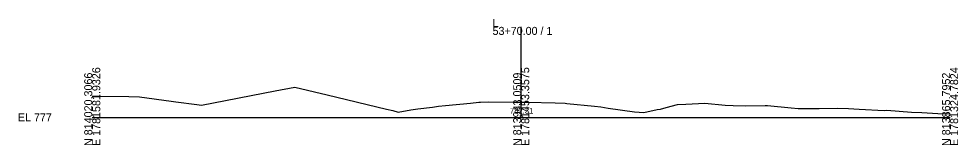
# Model space of a CAD drawing. Extents: x -26 to 7903, y -10 to 9573.
# Drawn here: x 7574.3 to 7902.8, y -9.7 to 34.4 of the extents above; entities that cross this region are included whole.
import ezdxf

# ---------------------------------------------------------------- set-up
doc = ezdxf.new("R2010")
doc.units = 0
for name, color, linetype in [('Exist Cross Section Cell', 7, 'Continuous'), ('Exist XS Center Line Elevation Label', 7, 'Continuous'), ('Exist XS Ground Line', 7, 'Continuous')]:
    doc.layers.add(name, color=color, linetype=linetype)

msp = doc.modelspace()

# ---------------------------------------------------------------- linework, layer by layer
at = {"layer": 'Exist Cross Section Cell'}
for p, q in [((7750, 0), (7750, 31.56)), ((7600, 0), (7750, 0)), ((7750, 0), (7900, 0))]:
    msp.add_line(p, q, dxfattribs=at)
at = {"layer": 'Exist XS Ground Line'}
for p, q in [((7663.97, 9.21), (7670.88, 10.52)), ((7670.88, 10.52), (7682.17, 7.82)), ((7600, 7.34), (7602.91, 7.37)), ((7602.91, 7.37), (7612.85, 7.28)), ((7612.85, 7.28), (7616.51, 7.11)), ((7616.51, 7.11), (7627.64, 5.69)), ((7638.15, 4.29), (7663.97, 9.21)), ((7682.17, 7.82), (7702.92, 2.91)), ((7627.64, 5.69), (7629.25, 5.41)), ((7629.25, 5.41), (7636.61, 4.48)), ((7636.61, 4.48), (7638.15, 4.29)), ((7713.81, 3.03), (7718.94, 3.6)), ((7718.94, 3.6), (7721.03, 3.92)), ((7721.03, 3.92), (7723.52, 4.14)), ((7723.52, 4.14), (7732.24, 4.99)), ((7732.24, 4.99), (7735.14, 5.26)), ((7735.14, 5.26), (7735.83, 5.29)), ((7735.83, 5.29), (7738.42, 5.41)), ((7738.42, 5.41), (7747.3, 5.34)), ((7747.3, 5.34), (7749.65, 5.32)), ((7749.65, 5.32), (7750, 5.31)), ((7750, 5.31), (7752.22, 5.26)), ((7752.22, 5.26), (7761.88, 5.08)), ((7761.88, 5.08), (7765.33, 4.92)), ((7765.33, 4.92), (7766.01, 4.89)), ((7766.01, 4.89), (7775.68, 3.92)), ((7775.68, 3.92), (7777.91, 3.69)), ((7777.91, 3.69), (7780.38, 3.25)), ((7798.7, 2.9), (7800.75, 3.48)), ((7800.75, 3.48), (7804.62, 4.44)), ((7804.62, 4.44), (7807.54, 4.57)), ((7807.54, 4.57), (7814.23, 4.95)), ((7814.23, 4.95), (7821.36, 4.25)), ((7821.36, 4.25), (7824.11, 4.15)), ((7824.11, 4.15), (7828.32, 3.97)), ((7828.32, 3.97), (7835.34, 4.14)), ((7835.34, 4.14), (7836.11, 4.14)), ((7836.11, 4.14), (7844.41, 3.28)), ((7702.92, 2.91), (7705.17, 2.37)), ((7705.17, 2.37), (7707.01, 1.85)), ((7707.01, 1.85), (7711.36, 2.64)), ((7711.36, 2.64), (7713.81, 3.03)), ((7780.38, 3.25), (7789.64, 1.95)), ((7789.64, 1.95), (7792.87, 1.68)), ((7792.87, 1.68), (7797.6, 2.75)), ((7797.6, 2.75), (7798.7, 2.9)), ((7844.41, 3.28), (7846.91, 3.13)), ((7846.91, 3.13), (7854.2, 3.14)), ((7854.2, 3.14), (7860.58, 3.2)), ((7860.58, 3.2), (7864.46, 3.09)), ((7864.46, 3.09), (7868.22, 2.83)), ((7868.22, 2.83), (7876.93, 2.35)), ((7876.93, 2.35), (7877.85, 2.55)), ((7877.85, 2.55), (7886.56, 1.86)), ((7886.56, 1.86), (7890.16, 1.65)), ((7890.16, 1.65), (7895.77, 1.4)), ((7895.77, 1.4), (7900, 1.19))]:
    msp.add_line(p, q, dxfattribs=at)

# ---------------------------------------------------------------- texts
at = {"layer": 'Exist Cross Section Cell'}
for s, p in [('L', (7740, 31.56)), ('53+70.00 / 1', (7740, 28.76)), ('EL 777', (7574, -1.4))]:
    msp.add_text(s, height=2.8, dxfattribs=at).set_placement(p)
for s, p in [('E 1781581.9326', (7602.8, -10)), ('E 1781453.3575', (7752.8, -10)), ('E 1781324.7824', (7902.8, -10)), ('N 814020.3066', (7600, -10)), ('N 813943.0509', (7750, -10)), ('N 813865.7952', (7900, -10))]:
    msp.add_text(s, height=2.8, rotation=90, dxfattribs=at).set_placement(p)
at = {"layer": 'Exist XS Center Line Elevation Label'}
msp.add_text('782.31', height=2, dxfattribs=at).set_placement((7746.08, 1.31))

doc.saveas('drawing.dxf')
